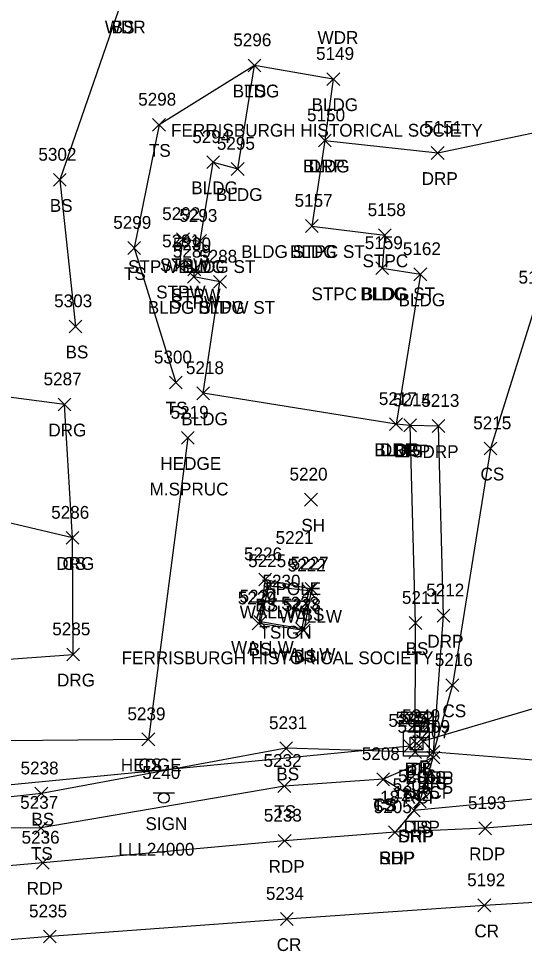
# Model space of a CAD drawing. Extents: x 1443912 to 1445411, y 621446 to 623693.
# Drawn here: x 1444608.9 to 1444688, y 622552.5 to 622698.4 of the extents above; entities that cross this region are included whole.
import ezdxf

# ---------------------------------------------------------------- set-up
doc = ezdxf.new("R2010")
doc.units = 0
for name, color, linetype in [('D_A', 7, 'Continuous'), ('D_C', 7, 'Continuous'), ('D_I', 7, 'Continuous'), ('D_TIC', 7, 'Continuous'), ('DCP', 7, 'Continuous'), ('DS', 7, 'Continuous'), ('L_A', 7, 'Continuous'), ('L_C', 7, 'Continuous'), ('L_I', 7, 'Continuous'), ('L_TIC', 7, 'Continuous'), ('LAHR', 7, 'Continuous'), ('LBC', 7, 'Continuous'), ('LBF', 7, 'Continuous'), ('LELB', 7, 'Continuous'), ('LFP', 7, 'Continuous'), ('LW', 7, 'Continuous'), ('P_A', 7, 'Continuous'), ('P_I', 7, 'Continuous'), ('P_TIC', 7, 'Continuous'), ('PET', 7, 'Continuous'), ('PRC', 7, 'Continuous'), ('PSP', 7, 'Continuous'), ('R_A', 7, 'Continuous'), ('R_I', 7, 'Continuous'), ('R_TIC', 7, 'Continuous'), ('RDG', 7, 'Continuous'), ('RDP', 7, 'Continuous'), ('S_A', 7, 'Continuous'), ('S_C', 7, 'Continuous'), ('S_I', 7, 'Continuous'), ('SSGN', 7, 'Continuous')]:
    doc.layers.add(name, color=color, linetype=linetype)

msp = doc.modelspace()

# ---------------------------------------------------------------- linework, layer by layer
at = {"layer": 'D_TIC'}
for points in [[(1444669.07, 622583.64), (1444671.07, 622585.64)], [(1444671.07, 622583.64), (1444669.07, 622585.64)], [(1444670.15, 622584.04), (1444672.15, 622586.04)], [(1444672.15, 622584.04), (1444670.15, 622586.04)], [(1444671.13, 622584.38), (1444673.13, 622586.38)], [(1444673.13, 622584.38), (1444671.13, 622586.38)]]:
    msp.add_lwpolyline(points, dxfattribs=at)
at = {"layer": 'DCP'}
for points in [[(1444730.93, 622602.71), (1444672.13, 622585.38)], [(1444670.07, 622584.64), (1444525.01, 622570.52)]]:
    msp.add_lwpolyline(points, dxfattribs=at)
at = {"layer": 'DS'}
for p, q in [((1444669.1, 622587.03), (1444673.1, 622587.03)), ((1444669.1, 622583.03), (1444669.1, 622587.03)), ((1444670.1, 622584.03), (1444670.1, 622586.03)), ((1444670.1, 622586.03), (1444672.1, 622586.03)), ((1444672.1, 622586.03), (1444672.1, 622584.03)), ((1444673.1, 622587.03), (1444673.1, 622583.03)), ((1444671.1, 622585.03), (1444671.1, 622585.03)), ((1444671.1, 622585.03), (1444671.1, 622585.03)), ((1444673.1, 622583.03), (1444669.1, 622583.03)), ((1444672.1, 622584.03), (1444670.1, 622584.03))]:
    msp.add_line(p, q, dxfattribs=at)
at = {"layer": 'L_TIC'}
for points in [[(1444644.79, 622690.07), (1444646.79, 622692.07)], [(1444646.79, 622690.07), (1444644.79, 622692.07)], [(1444644.79, 622690.07), (1444646.79, 622692.07)], [(1444646.79, 622690.07), (1444644.79, 622692.07)], [(1444644.79, 622690.07), (1444646.79, 622692.07)], [(1444646.79, 622690.07), (1444644.79, 622692.07)], [(1444657.11, 622687.93), (1444659.11, 622689.93)], [(1444659.11, 622687.93), (1444657.11, 622689.93)], [(1444657.11, 622687.93), (1444659.11, 622689.93)], [(1444659.11, 622687.93), (1444657.11, 622689.93)], [(1444629.86, 622680.78), (1444631.86, 622682.78)], [(1444631.86, 622680.78), (1444629.86, 622682.78)], [(1444655.77, 622678.33), (1444657.77, 622680.33)], [(1444657.77, 622678.33), (1444655.77, 622680.33)], [(1444638.32, 622674.93), (1444640.32, 622676.93)], [(1444640.32, 622674.93), (1444638.32, 622676.93)], [(1444642.16, 622673.88), (1444644.16, 622675.88)], [(1444644.16, 622673.88), (1444642.16, 622675.88)], [(1444614.34, 622672.17), (1444616.34, 622674.17)], [(1444616.34, 622672.17), (1444614.34, 622674.17)], [(1444653.74, 622664.96), (1444655.74, 622666.96)], [(1444655.74, 622664.96), (1444653.74, 622666.96)], [(1444653.74, 622664.96), (1444655.74, 622666.96)], [(1444655.74, 622664.96), (1444653.74, 622666.96)], [(1444633.61, 622662.89), (1444635.61, 622664.89)], [(1444635.61, 622662.89), (1444633.61, 622664.89)], [(1444636.29, 622662.61), (1444638.29, 622664.61)], [(1444638.29, 622662.61), (1444636.29, 622664.61)], [(1444636.29, 622662.61), (1444638.29, 622664.61)], [(1444638.29, 622662.61), (1444636.29, 622664.61)], [(1444665.17, 622663.51), (1444667.17, 622665.51)], [(1444667.17, 622663.51), (1444665.17, 622665.51)], [(1444625.97, 622661.52), (1444627.97, 622663.52)], [(1444627.97, 622661.52), (1444625.97, 622663.52)], [(1444633.03, 622658.63), (1444635.03, 622660.63)], [(1444635.03, 622658.63), (1444633.03, 622660.63)], [(1444635.39, 622658.16), (1444637.39, 622660.16)], [(1444637.39, 622658.16), (1444635.39, 622660.16)], [(1444664.73, 622658.35), (1444666.73, 622660.35)], [(1444666.73, 622658.35), (1444664.73, 622660.35)], [(1444664.73, 622658.35), (1444666.73, 622660.35)], [(1444666.73, 622658.35), (1444664.73, 622660.35)], [(1444635.29, 622657.02), (1444637.29, 622659.02)], [(1444637.29, 622657.02), (1444635.29, 622659.02)], [(1444670.72, 622657.41), (1444672.72, 622659.41)], [(1444672.72, 622657.41), (1444670.72, 622659.41)], [(1444639.39, 622656.23), (1444641.39, 622658.23)], [(1444641.39, 622656.23), (1444639.39, 622658.23)], [(1444639.39, 622656.23), (1444641.39, 622658.23)], [(1444641.39, 622656.23), (1444639.39, 622658.23)], [(1444616.8, 622649.26), (1444618.8, 622651.26)], [(1444618.8, 622649.26), (1444616.8, 622651.26)], [(1444632.49, 622640.47), (1444634.49, 622642.47)], [(1444634.49, 622640.47), (1444632.49, 622642.47)], [(1444636.75, 622638.8), (1444638.75, 622640.8)], [(1444638.75, 622638.8), (1444636.75, 622640.8)], [(1444666.91, 622633.96), (1444668.91, 622635.96)], [(1444668.91, 622633.96), (1444666.91, 622635.96)], [(1444669.12, 622633.78), (1444671.12, 622635.78)], [(1444671.12, 622633.78), (1444669.12, 622635.78)], [(1444634.37, 622631.82), (1444636.37, 622633.82)], [(1444636.37, 622631.82), (1444634.37, 622633.82)], [(1444681.68, 622630.17), (1444683.68, 622632.17)], [(1444683.68, 622630.17), (1444681.68, 622632.17)], [(1444653.61, 622622.16), (1444655.61, 622624.16)], [(1444655.61, 622622.16), (1444653.61, 622624.16)], [(1444616.32, 622616.18), (1444618.32, 622618.18)], [(1444618.32, 622616.18), (1444616.32, 622618.18)], [(1444646.47, 622609.69), (1444648.47, 622611.69)], [(1444648.47, 622609.69), (1444646.47, 622611.69)], [(1444646.47, 622609.69), (1444648.47, 622611.69)], [(1444648.47, 622609.69), (1444646.47, 622611.69)], [(1444647.05, 622608.61), (1444649.05, 622610.61)], [(1444649.05, 622608.61), (1444647.05, 622610.61)], [(1444647.05, 622608.61), (1444649.05, 622610.61)], [(1444649.05, 622608.61), (1444647.05, 622610.61)], [(1444653.24, 622607.93), (1444655.24, 622609.93)], [(1444655.24, 622607.93), (1444653.24, 622609.93)], [(1444653.24, 622607.93), (1444655.24, 622609.93)], [(1444655.24, 622607.93), (1444653.24, 622609.93)], [(1444653.69, 622608.23), (1444655.69, 622610.23)], [(1444655.69, 622608.23), (1444653.69, 622610.23)], [(1444645.44, 622602.79), (1444647.44, 622604.79)], [(1444647.44, 622602.79), (1444645.44, 622604.79)], [(1444645.44, 622602.79), (1444647.44, 622604.79)], [(1444647.44, 622602.79), (1444645.44, 622604.79)], [(1444645.7, 622603.07), (1444647.7, 622605.07)], [(1444647.7, 622603.07), (1444645.7, 622605.07)], [(1444669.96, 622602.87), (1444671.96, 622604.87)], [(1444671.96, 622602.87), (1444669.96, 622604.87)], [(1444652.21, 622601.97), (1444654.21, 622603.97)], [(1444654.21, 622601.97), (1444652.21, 622603.97)], [(1444652.48, 622601.69), (1444654.48, 622603.69)], [(1444654.48, 622601.69), (1444652.48, 622603.69)], [(1444675.72, 622593.14), (1444677.72, 622595.14)], [(1444677.72, 622593.14), (1444675.72, 622595.14)], [(1444628.19, 622584.68), (1444630.19, 622586.68)], [(1444630.19, 622584.68), (1444628.19, 622586.68)], [(1444628.19, 622584.68), (1444630.19, 622586.68)], [(1444630.19, 622584.68), (1444628.19, 622586.68)], [(1444649.75, 622583.28), (1444651.75, 622585.28)], [(1444651.75, 622583.28), (1444649.75, 622585.28)], [(1444669.91, 622582.7), (1444671.91, 622584.7)], [(1444671.91, 622582.7), (1444669.91, 622584.7)], [(1444669.91, 622582.7), (1444671.91, 622584.7)], [(1444671.91, 622582.7), (1444669.91, 622584.7)], [(1444672.75, 622582.7), (1444674.75, 622584.7)], [(1444674.75, 622582.7), (1444672.75, 622584.7)], [(1444672.74, 622581.84), (1444674.74, 622583.84)], [(1444674.74, 622581.84), (1444672.74, 622583.84)], [(1444664.9, 622578.43), (1444666.9, 622580.43)], [(1444666.9, 622578.43), (1444664.9, 622580.43)], [(1444664.9, 622578.43), (1444666.9, 622580.43)], [(1444666.9, 622578.43), (1444664.9, 622580.43)], [(1444649.46, 622577.37), (1444651.46, 622579.37)], [(1444651.46, 622577.37), (1444649.46, 622579.37)], [(1444611.47, 622576.2), (1444613.47, 622578.2)], [(1444613.47, 622576.2), (1444611.47, 622578.2)], [(1444670.63, 622574.96), (1444672.63, 622576.96)], [(1444672.63, 622574.96), (1444670.63, 622576.96)], [(1444611.41, 622570.82), (1444613.41, 622572.82)], [(1444613.41, 622570.82), (1444611.41, 622572.82)]]:
    msp.add_lwpolyline(points, dxfattribs=at)
at = {"layer": 'LAHR'}
msp.add_lwpolyline([(1444635.37, 622632.82), (1444629.19, 622585.68)], dxfattribs=at)
at = {"layer": 'LBC'}
for points in [[(1444637.29, 622663.61), (1444639.32, 622675.93), (1444643.16, 622674.88), (1444645.79, 622691.07)], [(1444658.11, 622688.93), (1444645.79, 622691.07)], [(1444658.11, 622688.93), (1444656.77, 622679.33), (1444654.74, 622665.96)], [(1444665.73, 622659.35), (1444671.72, 622658.41), (1444667.91, 622634.96), (1444637.75, 622639.8), (1444640.39, 622657.23)]]:
    msp.add_lwpolyline(points, dxfattribs=at)
at = {"layer": 'LBF'}
for points in [[(1444654.74, 622665.96), (1444666.17, 622664.51), (1444665.73, 622659.35)], [(1444640.39, 622657.23), (1444636.29, 622658.02), (1444636.39, 622659.16), (1444634.03, 622659.63), (1444634.61, 622663.89), (1444637.29, 622663.61)]]:
    msp.add_lwpolyline(points, dxfattribs=at)
at = {"layer": 'LELB'}
for points in [[(1444625.02, 622701.07), (1444615.34, 622673.17), (1444617.8, 622650.26)], [(1444645.79, 622691.07), (1444630.86, 622681.78), (1444626.97, 622662.52), (1444633.49, 622641.47)], [(1444692.04, 622681.11), (1444689.81, 622653.95), (1444682.68, 622631.17), (1444676.72, 622594.14)], [(1444670.91, 622583.7), (1444670.96, 622603.87), (1444670.12, 622634.78)], [(1444617.32, 622617.18), (1444587.05, 622624.31), (1444557.99, 622623.79), (1444533.14, 622619.94)], [(1444647.47, 622610.69), (1444654.69, 622609.23), (1444653.48, 622602.69), (1444646.44, 622603.79)], [(1444647.47, 622610.69), (1444646.44, 622603.79)], [(1444671.63, 622575.96), (1444665.9, 622579.43), (1444650.46, 622578.37), (1444612.41, 622571.82), (1444581.41, 622571.53), (1444560.15, 622567.9), (1444557.97, 622574.32), (1444550.78, 622583.65), (1444554.36, 622589.42), (1444560.77, 622593.82), (1444557.54, 622597.98), (1444569.9, 622600.16)], [(1444629.19, 622585.68), (1444585.01, 622585.22), (1444570.56, 622587.51), (1444560.77, 622593.82)], [(1444676.72, 622594.14), (1444673.75, 622583.7)], [(1444697.23, 622581.8), (1444673.75, 622583.7), (1444670.91, 622583.7), (1444650.75, 622584.28), (1444612.47, 622577.2), (1444597.79, 622575.59), (1444581.67, 622576.35), (1444561.57, 622574.94), (1444558.26, 622574.87), (1444555.28, 622578.78), (1444556.12, 622580.87), (1444562.14, 622578.88)], [(1444673.74, 622582.84), (1444665.9, 622579.43)]]:
    msp.add_lwpolyline(points, dxfattribs=at)
at = {"layer": 'LFP'}
for radius in [0.625, 0.0833]:
    msp.add_circle((1444651.77, 622613.24), radius, dxfattribs=at)
at = {"layer": 'LW'}
for points in [[(1444654.24, 622608.93), (1444653.21, 622602.97), (1444646.7, 622604.07), (1444648.05, 622609.61)], [(1444654.24, 622608.93), (1444648.05, 622609.61)]]:
    msp.add_lwpolyline(points, dxfattribs=at)
at = {"layer": 'P_TIC'}
for points in [[(1444669.71, 622573.57), (1444671.71, 622575.57)], [(1444671.71, 622573.57), (1444669.71, 622575.57)], [(1444680.85, 622570.77), (1444682.85, 622572.77)], [(1444682.85, 622570.77), (1444680.85, 622572.77)], [(1444666.76, 622570.14), (1444668.76, 622572.14)], [(1444668.76, 622570.14), (1444666.76, 622572.14)], [(1444666.76, 622570.14), (1444668.76, 622572.14)], [(1444668.76, 622570.14), (1444666.76, 622572.14)], [(1444649.5, 622568.81), (1444651.5, 622570.81)], [(1444651.5, 622568.81), (1444649.5, 622570.81)], [(1444611.69, 622565.37), (1444613.69, 622567.37)], [(1444613.69, 622565.37), (1444611.69, 622567.37)], [(1444680.72, 622558.72), (1444682.72, 622560.72)], [(1444682.72, 622558.72), (1444680.72, 622560.72)], [(1444649.83, 622556.58), (1444651.83, 622558.58)], [(1444651.83, 622556.58), (1444649.83, 622558.58)], [(1444612.8, 622553.84), (1444614.8, 622555.84)], [(1444614.8, 622553.84), (1444612.8, 622555.84)]]:
    msp.add_lwpolyline(points, dxfattribs=at)
at = {"layer": 'PET'}
msp.add_lwpolyline([(1444727.75, 622590.13), (1444719.16, 622580.43), (1444710.14, 622575.73), (1444699.63, 622573.2), (1444681.85, 622571.77), (1444667.76, 622571.14), (1444650.5, 622569.81), (1444612.69, 622566.37), (1444582.45, 622563.73), (1444564.11, 622562), (1444525.39, 622558.42), (1444488.31, 622554.6), (1444447.09, 622551.06), (1444415.95, 622548.51), (1444383.77, 622544.98), (1444340.89, 622540.77), (1444296.33, 622536.74), (1444247.14, 622532.77)], dxfattribs=at)
at = {"layer": 'PRC'}
msp.add_lwpolyline([(1444719.77, 622561.99), (1444681.72, 622559.72), (1444650.83, 622557.58), (1444613.8, 622554.84), (1444583.05, 622552.28), (1444545.98, 622548.57), (1444490.19, 622543.66), (1444448.69, 622540.02), (1444415.77, 622536.99), (1444385.19, 622533.95), (1444342.42, 622530.03), (1444296.8, 622526.08), (1444247.95, 622521.6), (1444210.22, 622518.45), (1444165.33, 622514.18), (1444110.47, 622509.68), (1444063.9, 622505.59), (1444012.84, 622501.59), (1443966.33, 622497.17), (1443919.63, 622492.61)], dxfattribs=at)
at = {"layer": 'PSP'}
msp.add_lwpolyline([(1444764.56, 622721.65), (1444754.92, 622687.33), (1444747.04, 622659.57), (1444737.91, 622624.67), (1444735.15, 622617.37), (1444730.83, 622603.71), (1444724.93, 622592.98), (1444717.73, 622583.9), (1444710.49, 622580.34), (1444707.37, 622579.31), (1444699.32, 622577.29), (1444670.71, 622574.57), (1444667.76, 622571.14)], dxfattribs=at)
at = {"layer": 'R_TIC'}
for points in [[(1444655.77, 622678.33), (1444657.77, 622680.33)], [(1444657.77, 622678.33), (1444655.77, 622680.33)], [(1444673.43, 622676.38), (1444675.43, 622678.38)], [(1444675.43, 622676.38), (1444673.43, 622678.38)], [(1444615.07, 622637.05), (1444617.07, 622639.05)], [(1444617.07, 622637.05), (1444615.07, 622639.05)], [(1444666.91, 622633.96), (1444668.91, 622635.96)], [(1444668.91, 622633.96), (1444666.91, 622635.96)], [(1444669.12, 622633.78), (1444671.12, 622635.78)], [(1444671.12, 622633.78), (1444669.12, 622635.78)], [(1444673.55, 622633.68), (1444675.55, 622635.68)], [(1444675.55, 622633.68), (1444673.55, 622635.68)], [(1444616.32, 622616.18), (1444618.32, 622618.18)], [(1444618.32, 622616.18), (1444616.32, 622618.18)], [(1444674.33, 622604.03), (1444676.33, 622606.03)], [(1444676.33, 622604.03), (1444674.33, 622606.03)], [(1444616.43, 622597.95), (1444618.43, 622599.95)], [(1444618.43, 622597.95), (1444616.43, 622599.95)], [(1444672.75, 622582.7), (1444674.75, 622584.7)], [(1444674.75, 622582.7), (1444672.75, 622584.7)], [(1444672.74, 622581.84), (1444674.74, 622583.84)], [(1444674.74, 622581.84), (1444672.74, 622583.84)], [(1444670.63, 622574.96), (1444672.63, 622576.96)], [(1444672.63, 622574.96), (1444670.63, 622576.96)], [(1444669.71, 622573.57), (1444671.71, 622575.57)], [(1444671.71, 622573.57), (1444669.71, 622575.57)]]:
    msp.add_lwpolyline(points, dxfattribs=at)
at = {"layer": 'RDG'}
msp.add_lwpolyline([(1444560.48, 622563.48), (1444552.02, 622570.18), (1444547.86, 622583.98), (1444548.7, 622599.66), (1444554.69, 622609.39), (1444569.39, 622610.94), (1444569.9, 622600.16), (1444581.46, 622596.36), (1444617.43, 622598.95), (1444617.32, 622617.18), (1444616.07, 622638.05), (1444588.71, 622641.66), (1444550.37, 622641.84), (1444535.64, 622641.83), (1444533.14, 622619.94), (1444531.08, 622601.59), (1444534.37, 622574.32), (1444533.53, 622561.1)], dxfattribs=at)
at = {"layer": 'RDP'}
for points in [[(1444656.77, 622679.33), (1444674.43, 622677.38), (1444692.04, 622681.11), (1444706.46, 622681.16), (1444717.45, 622670.41), (1444702.2, 622642.97), (1444697.07, 622619.06), (1444692.84, 622602.58), (1444695.16, 622589.38), (1444697.23, 622581.8), (1444699.32, 622577.29)], [(1444670.71, 622574.57), (1444671.63, 622575.96), (1444673.74, 622582.84), (1444673.75, 622583.7), (1444675.33, 622605.03), (1444674.55, 622634.68), (1444670.12, 622634.78), (1444667.91, 622634.96)]]:
    msp.add_lwpolyline(points, dxfattribs=at)
at = {"layer": 'SSGN'}
for p, q in [((1444646.36, 622607.35), (1444654.95, 622607.35)), ((1444650.38, 622606.45), (1444650.38, 622606.45)), ((1444629.96, 622577.34), (1444633.29, 622577.34)), ((1444631.61, 622576.51), (1444631.61, 622576.51))]:
    msp.add_line(p, q, dxfattribs=at)
for centre in [(1444648.02, 622606.52), (1444653.23, 622606.45), (1444631.61, 622576.51)]:
    msp.add_circle(centre, 0.833, dxfattribs=at)

# ---------------------------------------------------------------- texts
at = {"layer": 'D_A'}
for s, p in [('DIB', (1444669.25, 622580.04)), ('P', (1444669.45, 622579.64)), ('DI', (1444670.16, 622580.03)), ('P', (1444671.51, 622580.38))]:
    msp.add_text(s, height=2, dxfattribs=at).set_placement(p)
at = {"layer": 'D_C'}
for s, p in [('18 RCP', (1444667.49, 622576.38)), ('18 RCP', (1444665.43, 622575.64)), ('2X2', (1444668.68, 622576.03))]:
    msp.add_text(s, height=2, dxfattribs=at).set_placement(p)
at = {"layer": 'D_I'}
for s, p in [('5252', (1444667.84, 622588.03)), ('5251', (1444668.46, 622588.04)), ('5249', (1444668.86, 622588.38)), ('5250', (1444666.72, 622587.64))]:
    msp.add_text(s, height=2, dxfattribs=at).set_placement(p)
at = {"layer": 'L_A'}
for s, p in [('WDR', (1444622.39, 622696.07)), ('BS', (1444623.46, 622696.07)), ('WDR', (1444655.64, 622694.44)), ('BLDG', (1444642.38, 622686.07)), ('BLDG', (1444642.38, 622686.07)), ('TS', (1444644.2, 622686.07)), ('BLDG', (1444654.7, 622683.93)), ('BLDG', (1444654.7, 622683.93)), ('TS', (1444629.27, 622676.78)), ('BLDG', (1444653.36, 622674.33)), ('BLDG', (1444635.91, 622670.93)), ('BLDG', (1444639.75, 622669.88)), ('BS', (1444613.78, 622668.17)), ('BLDG STPC ST', (1444643.71, 622660.96)), ('BLDG', (1444651.33, 622660.96)), ('STPC', (1444662.68, 622659.51)), ('STPW BLDG ST', (1444626.01, 622658.61)), ('STPW', (1444631, 622658.89)), ('BLDG', (1444633.88, 622658.61)), ('TS', (1444625.37, 622657.52)), ('STPW', (1444630.42, 622654.63)), ('STPW', (1444632.78, 622654.16)), ('STPC BLDG ST', (1444654.69, 622654.35)), ('BLDG', (1444662.32, 622654.35)), ('BLDG STPW ST', (1444629.1, 622652.23)), ('STPW', (1444632.68, 622653.02)), ('BLDG', (1444636.98, 622652.23)), ('BLDG', (1444668.31, 622653.41)), ('BS', (1444616.24, 622645.26)), ('TS', (1444631.9, 622636.47)), ('BLDG', (1444634.34, 622634.8)), ('BLDG', (1444664.5, 622629.96)), ('BS', (1444668.56, 622629.78)), ('HEDGE', (1444631.07, 622627.82)), ('CS', (1444681.12, 622626.17)), ('SH', (1444653.1, 622618.16)), ('CS', (1444615.76, 622612.18)), ('FPOLE', (1444647.44, 622608.24)), ('BS', (1444645.91, 622605.69)), ('BS', (1444645.91, 622605.69)), ('WALLW', (1444643.47, 622604.61)), ('WALLW', (1444643.47, 622604.61)), ('BS', (1444653.14, 622604.23)), ('WALLW', (1444649.66, 622603.93)), ('WALLW', (1444649.66, 622603.93)), ('WALLW', (1444642.12, 622599.07)), ('BS', (1444644.88, 622598.79)), ('BS', (1444644.88, 622598.79)), ('BS', (1444669.4, 622598.87)), ('WALLW', (1444648.63, 622597.97)), ('BS', (1444651.92, 622597.69)), ('CS', (1444675.16, 622589.14)), ('HEDGE', (1444624.89, 622580.68)), ('CS', (1444627.63, 622580.68)), ('BS', (1444649.2, 622579.28)), ('BS', (1444669.35, 622578.7)), ('BS', (1444669.35, 622578.7)), ('CS', (1444672.18, 622577.84)), ('BS', (1444672.2, 622578.7)), ('TS', (1444648.87, 622573.37)), ('TS', (1444664.31, 622574.43)), ('CS', (1444664.34, 622574.43)), ('BS', (1444610.91, 622572.2)), ('TS', (1444670.04, 622570.96)), ('TS', (1444610.82, 622566.82))]:
    msp.add_text(s, height=2, dxfattribs=at).set_placement(p)
at = {"layer": 'L_C'}
for s, p in [('FERRISBURGH HISTORICAL SOCIETY', (1444632.74, 622679.93)), ('FERRISBURGH HISTORICAL SOCIETY', (1444632.74, 622679.93)), ('M.SPRUC', (1444629.39, 622623.82))]:
    msp.add_text(s, height=2, dxfattribs=at).set_placement(p)
at = {"layer": 'L_I'}
for s, p in [('5296', (1444642.47, 622694.07)), ('5296', (1444642.47, 622694.07)), ('5296', (1444642.47, 622694.07)), ('5149', (1444655.41, 622691.93)), ('5149', (1444655.41, 622691.93)), ('5298', (1444627.6, 622684.78)), ('5150', (1444654, 622682.33)), ('5294', (1444636.06, 622678.93)), ('5295', (1444639.9, 622677.88)), ('5302', (1444612, 622676.17)), ('5157', (1444652.05, 622668.96)), ('5157', (1444652.05, 622668.96)), ('5292', (1444631.35, 622666.89)), ('5158', (1444663.48, 622667.51)), ('5299', (1444623.7, 622665.52)), ('5293', (1444634.03, 622666.61)), ('5293', (1444634.03, 622666.61)), ('5291', (1444631.34, 622662.63)), ('5159', (1444663.02, 622662.35)), ('5159', (1444663.02, 622662.35)), ('5289', (1444633.02, 622661.02)), ('5290', (1444633.04, 622662.16)), ('5162', (1444668.98, 622661.41)), ('5288', (1444637.13, 622660.23)), ('5288', (1444637.13, 622660.23)), ('5156', (1444687.06, 622656.95)), ('5303', (1444614.46, 622653.26)), ('5300', (1444630.06, 622644.47)), ('5218', (1444635.06, 622642.8)), ('5217', (1444665.22, 622637.96)), ('5214', (1444667.42, 622637.78)), ('5219', (1444632.67, 622635.82)), ('5215', (1444679.98, 622634.17)), ('5220', (1444651.26, 622626.16)), ('5286', (1444614, 622620.18)), ('5221', (1444649.08, 622616.24)), ('5226', (1444644.15, 622613.69)), ('5226', (1444644.15, 622613.69)), ('5225', (1444644.79, 622612.61)), ('5225', (1444644.79, 622612.61)), ('5222', (1444650.98, 622611.93)), ('5222', (1444650.98, 622611.93)), ('5227', (1444651.43, 622612.23)), ('5224', (1444643.44, 622607.07)), ('5229', (1444643.17, 622606.79)), ('5229', (1444643.17, 622606.79)), ('5223', (1444649.95, 622605.97)), ('5228', (1444650.22, 622605.69)), ('5211', (1444668.83, 622606.87)), ('5216', (1444673.97, 622597.14)), ('5239', (1444625.92, 622588.68)), ('5239', (1444625.92, 622588.68)), ('5231', (1444648.06, 622587.28)), ('5210', (1444668.13, 622586.7)), ('5210', (1444668.13, 622586.7)), ('5209', (1444670.41, 622586.7)), ('5207', (1444670.4, 622585.84)), ('5208', (1444662.56, 622582.43)), ('5208', (1444662.56, 622582.43)), ('5232', (1444647.2, 622581.37)), ('5238', (1444609.21, 622580.2)), ('5206', (1444668.23, 622578.96)), ('5237', (1444609.15, 622574.82))]:
    msp.add_text(s, height=2, dxfattribs=at).set_placement(p)
at = {"layer": 'P_A'}
for s, p in [('SHP', (1444668.25, 622569.57)), ('SHP', (1444665.3, 622566.14)), ('RDP', (1444665.25, 622566.14)), ('RDP', (1444679.34, 622566.77)), ('RDP', (1444647.99, 622564.81)), ('RDP', (1444610.18, 622561.37)), ('CR', (1444680.16, 622554.72)), ('CR', (1444649.26, 622552.58))]:
    msp.add_text(s, height=2, dxfattribs=at).set_placement(p)
at = {"layer": 'P_I'}
for s, p in [('5204', (1444667.38, 622577.57)), ('5205', (1444664.43, 622574.14)), ('5205', (1444664.43, 622574.14)), ('5193', (1444679.16, 622574.77)), ('5233', (1444647.24, 622572.81)), ('5236', (1444609.37, 622569.37)), ('5192', (1444679.03, 622562.72)), ('5234', (1444647.57, 622560.58)), ('5235', (1444610.54, 622557.84))]:
    msp.add_text(s, height=2, dxfattribs=at).set_placement(p)
at = {"layer": 'R_A'}
for s, p in [('DRP', (1444654.26, 622674.33)), ('DRP', (1444671.92, 622672.38)), ('DRG', (1444613.56, 622633.05)), ('DRP', (1444665.4, 622629.96)), ('DRP', (1444667.6, 622629.78)), ('DRP', (1444672.04, 622629.68)), ('DRG', (1444614.8, 622612.18)), ('DRP', (1444672.81, 622600.03)), ('DRG', (1444614.91, 622593.95)), ('DRP', (1444671.23, 622577.84)), ('DRP', (1444671.24, 622578.7)), ('DRP', (1444669.12, 622570.96)), ('DRP', (1444668.2, 622569.57))]:
    msp.add_text(s, height=2, dxfattribs=at).set_placement(p)
at = {"layer": 'R_I'}
for s, p in [('5150', (1444654, 622682.33)), ('5151', (1444672.3, 622680.38)), ('5287', (1444612.81, 622641.05)), ('5217', (1444665.22, 622637.96)), ('5214', (1444667.42, 622637.78)), ('5213', (1444671.86, 622637.68)), ('5286', (1444614, 622620.18)), ('5212', (1444672.63, 622608.03)), ('5285', (1444614.17, 622601.95)), ('5209', (1444670.41, 622586.7)), ('5207', (1444670.4, 622585.84)), ('5206', (1444668.23, 622578.96)), ('5204', (1444667.38, 622577.57))]:
    msp.add_text(s, height=2, dxfattribs=at).set_placement(p)
at = {"layer": 'S_A'}
for s, p in [('TSIGN', (1444646.56, 622601.43)), ('SIGN', (1444628.74, 622571.49))]:
    msp.add_text(s, height=2, dxfattribs=at).set_placement(p)
at = {"layer": 'S_C'}
for s, p in [('FERRISBURGH HISTORICAL SOCIETY', (1444625.01, 622597.43)), ('LLL24000', (1444624.49, 622567.49))]:
    msp.add_text(s, height=2, dxfattribs=at).set_placement(p)
at = {"layer": 'S_I'}
for s, p in [('5230', (1444647.03, 622609.43)), ('5240', (1444628.24, 622579.49))]:
    msp.add_text(s, height=2, dxfattribs=at).set_placement(p)

doc.saveas('drawing.dxf')
